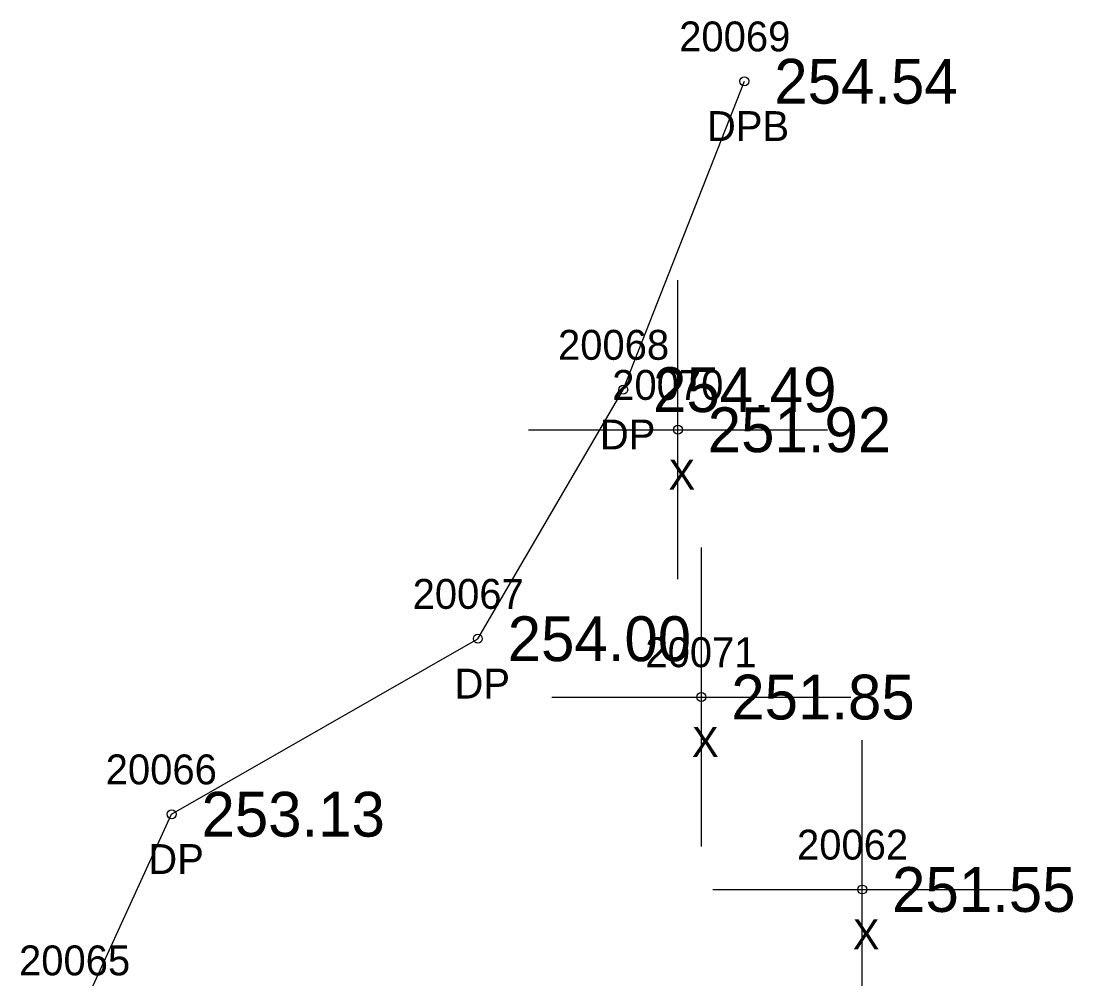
# Model space of a CAD drawing. Extents: x 1961330 to 1962287, y 800294 to 801079.
# Drawn here: x 1962087.45 to 1962122.64, y 800505.6 to 800537.66 of the extents above; entities that cross this region are included whole.
import ezdxf

# ---------------------------------------------------------------- set-up
doc = ezdxf.new("R2010")
doc.units = 0
for name, color, linetype in [('RD_EX_Driveway', 7, 'Continuous'), ('RD_EX_Driveway_txCode', 7, 'Continuous'), ('RD_EX_Misc', 7, 'Continuous'), ('RD_EX_Misc_txCode', 7, 'Continuous'), ('RD_EX_TX_Driveway_ELEV', 7, 'Continuous'), ('RD_EX_TX_Misc_ELEV', 7, 'Continuous'), ('RD_SMD_Locator', 7, 'Continuous')]:
    doc.layers.add(name, color=color, linetype=linetype)

msp = doc.modelspace()

# ---------------------------------------------------------------- linework, layer by layer
at = {"layer": 'RD_EX_Driveway'}
msp.add_lwpolyline([(1962091.521, 800497.238), (1962089.567, 800504.726), (1962092.491, 800511.116), (1962102.735, 800516.988), (1962107.598, 800525.321), (1962111.652, 800535.64)], dxfattribs=at)
at = {"layer": 'RD_EX_Misc'}
for p, q in [((1962109.428, 800518.98), (1962109.428, 800528.98)), ((1962104.428, 800523.98), (1962114.428, 800523.98)), ((1962110.214, 800510.036), (1962110.214, 800520.036)), ((1962105.214, 800515.036), (1962115.214, 800515.036)), ((1962115.594, 800503.598), (1962115.594, 800513.598)), ((1962110.594, 800508.598), (1962120.594, 800508.598))]:
    msp.add_line(p, q, dxfattribs=at)
at = {"layer": 'RD_SMD_Locator'}
for centre in [(1962111.652, 800535.64), (1962107.598, 800525.321), (1962109.428, 800523.98), (1962102.735, 800516.988), (1962110.214, 800515.036), (1962092.491, 800511.116), (1962115.594, 800508.598)]:
    msp.add_circle(centre, 0.15, dxfattribs=at)

# ---------------------------------------------------------------- texts
at = {"layer": 'RD_EX_Driveway_txCode'}
for s, p in [('20069', (1962109.471, 800536.64)), ('DPB', (1962110.4, 800533.64)), ('20068', (1962105.417, 800526.321)), ('DP', (1962106.818, 800523.321)), ('20067', (1962100.554, 800517.988)), ('DP', (1962101.955, 800514.988)), ('20066', (1962090.286, 800512.116)), ('DP', (1962091.711, 800509.116)), ('20065', (1962087.386, 800505.726))]:
    msp.add_text(s, height=1, dxfattribs=at).set_placement(p)
at = {"layer": 'RD_EX_Misc_txCode'}
for s, p in [('20070', (1962107.231, 800524.98)), ('X', (1962109.113, 800521.98)), ('20071', (1962108.34, 800516.036)), ('X', (1962109.899, 800513.036)), ('20062', (1962113.413, 800509.598)), ('X', (1962115.279, 800506.598))]:
    msp.add_text(s, height=1, dxfattribs=at).set_placement(p)
at = {"layer": 'RD_EX_TX_Driveway_ELEV'}
for s, p in [('254.54', (1962112.652, 800534.89)), ('254.49', (1962108.598, 800524.571)), ('254.00', (1962103.735, 800516.238)), ('253.13', (1962093.491, 800510.366))]:
    msp.add_text(s, height=1.5, dxfattribs=at).set_placement(p)
at = {"layer": 'RD_EX_TX_Misc_ELEV'}
for s, p in [('251.92', (1962110.428, 800523.23)), ('251.85', (1962111.214, 800514.286)), ('251.55', (1962116.594, 800507.848))]:
    msp.add_text(s, height=1.5, dxfattribs=at).set_placement(p)

doc.saveas('drawing.dxf')
